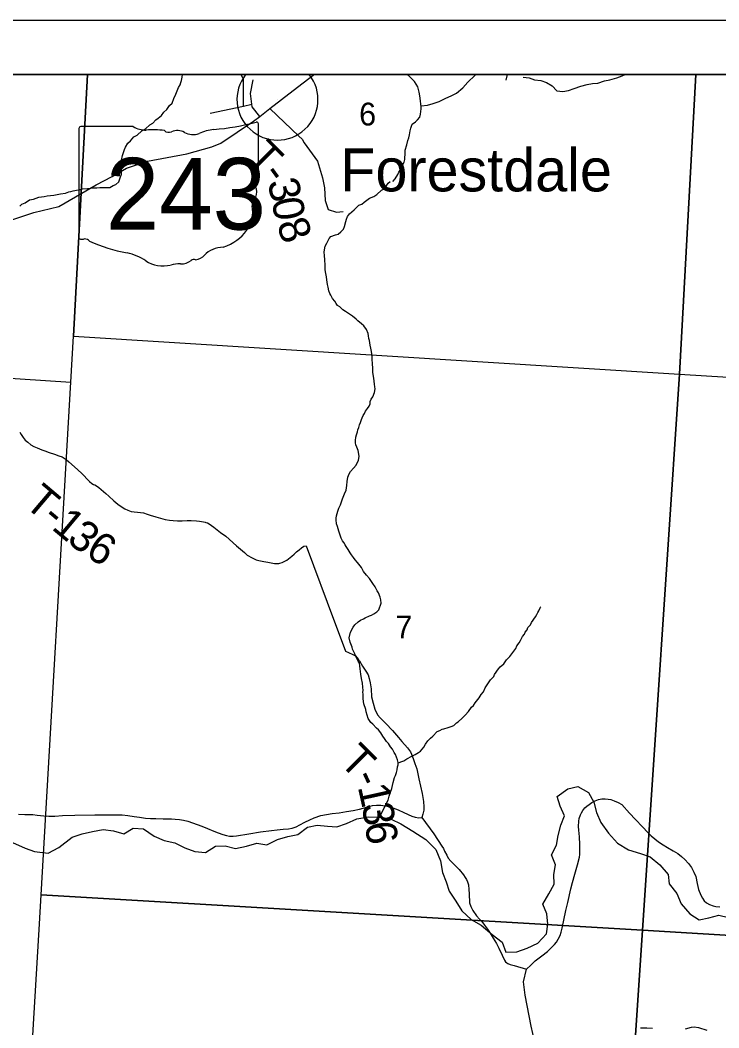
# Model space of a CAD drawing. Extents: x 0 to 45.4, y -2.2 to 22.
# Drawn here: x 2.846 to 4.13, y 19.147 to 21 of the extents above; entities that cross this region are included whole.
import ezdxf

# ---------------------------------------------------------------- set-up
doc = ezdxf.new("R2010")
doc.units = 0
for name, color, linetype in [('GM_X_Corporation', 7, 'Continuous'), ('GM_X_County_Road', 7, 'Continuous'), ('GM_X_Minor_River', 7, 'Continuous'), ('GM_X_Section_Text', 7, 'Continuous'), ('GM_X_State_Location', 7, 'Continuous'), ('GM_X_State_Route', 7, 'Continuous'), ('GM_X_State_Shield', 7, 'Continuous'), ('GM_X_Township_Road', 7, 'Continuous'), ('GM_X_Township_Road_Text', 7, 'Continuous'), ('GM_X_Unincorporated_Location', 7, 'Continuous'), ('GM_X_Unincorporated_Text', 7, 'Continuous'), ('GM_X_US_Shield', 7, 'Continuous'), ('SH_Data', 7, 'Continuous')]:
    doc.layers.add(name, color=color, linetype=linetype)

msp = doc.modelspace()

# ---------------------------------------------------------------- linework, layer by layer
at = {"layer": 'GM_X_Corporation'}
for points in [[(8.9, 20.9), (2.1, 20.9), (2.1, 19.3454), (2.1562, 19.32), (2.2951, 19.2289), (2.4503, 19.1527), (2.5862, 19.0536)], [(6.2942, 20.9), (2.1, 20.9), (2.1, 19.3454), (2.1562, 19.32), (2.2951, 19.2289), (2.4503, 19.1527), (2.5862, 19.0536)], [(2.8526, 18.8566), (2.8813, 19.3385), (2.8847, 19.3915), (3.9891, 19.3268), (3.9206, 18.2985)]]:
    msp.add_lwpolyline(points, dxfattribs=at)
for points in [[(2.9697, 20.9), (2.1, 20.9), (2.1, 20.3896), (2.9392, 20.3345), (2.9438, 20.419)], [(4.0874, 20.9), (2.9697, 20.9), (2.9438, 20.419), (4.0572, 20.3489)], [(5.1793, 20.9), (4.0874, 20.9), (4.0572, 20.3489), (5.1309, 20.2827)], [(2.9438, 20.419), (4.0572, 20.3489), (3.9891, 19.3268), (2.8847, 19.3915), (2.9392, 20.3345)], [(4.0572, 20.3489), (5.1309, 20.2827), (5.073, 19.2613), (3.9891, 19.3268)], [(5.073, 19.2613), (5.0121, 18.2353), (3.9206, 18.2985), (3.9891, 19.3268)]]:
    msp.add_lwpolyline(points, close=True, dxfattribs=at)
at = {"layer": 'GM_X_County_Road'}
msp.add_lwpolyline([(3.7907, 19.1234), (3.7847, 19.1505), (3.774, 19.2071), (3.7709, 19.2319), (3.7761, 19.2553), (3.784, 19.2626), (3.7924, 19.2704), (3.8044, 19.2797), (3.8148, 19.2874), (3.8227, 19.2954), (3.8279, 19.3004), (3.8314, 19.3046), (3.8344, 19.31), (3.8378, 19.3172), (3.8398, 19.3232), (3.8419, 19.3304), (3.8486, 19.3631), (3.852, 19.3775), (3.8578, 19.4026), (3.8607, 19.4146), (3.8651, 19.43), (3.8701, 19.4468), (3.8734, 19.4612), (3.8741, 19.4658), (3.874, 19.4842), (3.8736, 19.4985), (3.8726, 19.5108), (3.8719, 19.5175), (3.8721, 19.5274), (3.8731, 19.532), (3.8756, 19.539), (3.8772, 19.5426), (3.8799, 19.547), (3.8835, 19.5516), (3.8871, 19.555), (3.8912, 19.5579), (3.8965, 19.5616), (3.9026, 19.5648), (3.9083, 19.5669), (3.9149, 19.568), (3.9208, 19.5683), (3.926, 19.5677), (3.9314, 19.567), (3.9375, 19.5647), (3.9445, 19.5618), (3.9512, 19.5576), (3.9657, 19.5422), (3.9764, 19.5301), (3.9895, 19.5165), (3.9991, 19.5061), (4.0053, 19.5003), (4.0122, 19.4949), (4.0189, 19.4891), (4.0272, 19.4839), (4.0352, 19.4785), (4.0459, 19.4729), (4.054, 19.4676), (4.0608, 19.4624), (4.067, 19.4568), (4.0737, 19.4495), (4.0792, 19.4418), (4.0838, 19.4335), (4.0871, 19.4253), (4.0899, 19.4128), (4.0924, 19.4014), (4.0963, 19.3914), (4.0995, 19.3856), (4.1029, 19.3809), (4.1072, 19.3771), (4.1125, 19.374), (4.1189, 19.3715), (4.1243, 19.3705), (4.1315, 19.3699)], dxfattribs=at)
at = {"layer": 'GM_X_Minor_River'}
for points in [[(3.0338, 20.7514), (3.0377, 20.7624), (3.0393, 20.7665), (3.044, 20.7736), (3.0486, 20.7781), (3.0552, 20.7852), (3.0613, 20.7885), (3.0698, 20.7964), (3.0763, 20.8), (3.084, 20.8075), (3.0897, 20.8104), (3.0955, 20.8168), (3.0997, 20.8198), (3.1055, 20.8246), (3.1098, 20.831), (3.1155, 20.8355), (3.1206, 20.8433), (3.1256, 20.8471), (3.1284, 20.8561), (3.1319, 20.864), (3.1343, 20.8701), (3.1371, 20.8761), (3.1402, 20.881), (3.141, 20.8851), (3.1426, 20.8893), (3.1439, 20.895), (3.1444, 20.9)], [(3.531, 20.7031), (3.5352, 20.7083), (3.5399, 20.7162), (3.5419, 20.7204), (3.547, 20.7283), (3.5493, 20.7347), (3.5513, 20.7388), (3.5525, 20.7437), (3.5531, 20.7566), (3.5532, 20.7612), (3.5564, 20.771), (3.5584, 20.7786), (3.5601, 20.7838), (3.5613, 20.7891), (3.5625, 20.7963), (3.5638, 20.8016), (3.5662, 20.8088), (3.5723, 20.8129), (3.5762, 20.817), (3.58, 20.8219), (3.5816, 20.8271), (3.5826, 20.837), (3.583, 20.8412), (3.5824, 20.8457), (3.5817, 20.8514), (3.58, 20.8606), (3.579, 20.8678), (3.5769, 20.8773), (3.5706, 20.8873), (3.5654, 20.892), (3.5598, 20.8974), (3.5563, 20.9)], [(3.5829, 20.8423), (3.5943, 20.8435), (3.6049, 20.8466), (3.6158, 20.8507), (3.628, 20.8568), (3.6378, 20.8606), (3.6476, 20.8655), (3.659, 20.8757), (3.6685, 20.8859), (3.6813, 20.8984), (3.683, 20.9)], [(3.7699, 20.8951), (3.7809, 20.8939), (3.7911, 20.8901), (3.8028, 20.889), (3.8127, 20.8855), (3.8232, 20.8795), (3.8319, 20.87), (3.8429, 20.8689), (3.8535, 20.8708), (3.8641, 20.8742), (3.8759, 20.8787), (3.8876, 20.8814), (3.8974, 20.8833), (3.9073, 20.884), (3.9194, 20.8882), (3.9292, 20.8905), (3.9421, 20.8942), (3.9519, 20.8976), (3.9578, 20.9)], [(2.8454, 20.6578), (2.8492, 20.6619), (2.8553, 20.6641), (2.863, 20.6696), (2.8706, 20.671), (2.8801, 20.6747), (2.89, 20.676), (2.8957, 20.6771), (2.9078, 20.678), (2.9204, 20.6808), (2.9291, 20.6818), (2.9352, 20.6844), (2.9394, 20.6847), (2.9436, 20.6861), (2.9497, 20.6871), (2.9539, 20.6882), (2.9603, 20.6896), (2.9698, 20.6906), (2.9751, 20.6909), (2.9804, 20.6916), (2.9869, 20.6918), (2.9926, 20.6921), (2.9979, 20.6924), (3.0062, 20.6923), (3.0108, 20.6926), (3.0172, 20.6959), (3.0218, 20.6977), (3.0272, 20.7029), (3.03, 20.7101), (3.032, 20.7169), (3.0325, 20.7218), (3.033, 20.7298), (3.0323, 20.7347), (3.0321, 20.7427), (3.0338, 20.7514)], [(3.4738, 20.6619), (3.478, 20.6652), (3.4876, 20.6727), (3.496, 20.676), (3.5014, 20.6793), (3.5099, 20.6871), (3.5148, 20.6901), (3.5183, 20.6946), (3.5222, 20.7002), (3.5261, 20.7035)], [(3.4421, 20.1293), (3.4449, 20.1357), (3.4453, 20.1403), (3.4461, 20.1441), (3.447, 20.1517), (3.4483, 20.16), (3.4507, 20.166), (3.4527, 20.1702), (3.4584, 20.1761), (3.4631, 20.1818), (3.4674, 20.1908), (3.469, 20.1976), (3.4684, 20.2022), (3.4673, 20.2086), (3.4648, 20.2148), (3.4626, 20.2194), (3.4623, 20.2228), (3.4624, 20.227), (3.4629, 20.233), (3.4637, 20.2376), (3.4657, 20.2428), (3.4665, 20.247), (3.4681, 20.2512), (3.4697, 20.2561), (3.4713, 20.2602), (3.4729, 20.2655), (3.4741, 20.2689), (3.4761, 20.273), (3.4788, 20.2768), (3.4807, 20.2813), (3.4839, 20.2862), (3.487, 20.2903), (3.4889, 20.2945), (3.489, 20.299), (3.491, 20.3032), (3.4937, 20.3073), (3.4973, 20.3152), (3.4981, 20.322), (3.4978, 20.3258), (3.4971, 20.3308), (3.4958, 20.3418), (3.4948, 20.3483), (3.4941, 20.3525), (3.4942, 20.3563), (3.4939, 20.3608), (3.4936, 20.3677), (3.493, 20.3772), (3.4928, 20.3821), (3.4914, 20.3909), (3.49, 20.3966), (3.4889, 20.4023), (3.488, 20.4107), (3.4869, 20.4149), (3.4858, 20.4194), (3.4852, 20.424), (3.4823, 20.4313), (3.4774, 20.4378), (3.4733, 20.4417), (3.4666, 20.4471), (3.4633, 20.4502), (3.4565, 20.4556), (3.4528, 20.4584), (3.4438, 20.4642), (3.439, 20.4673), (3.4334, 20.4731), (3.4292, 20.4755), (3.4267, 20.4793), (3.4241, 20.4835), (3.42, 20.4882), (3.4171, 20.4943), (3.4149, 20.4977), (3.4134, 20.5023), (3.4117, 20.5088), (3.4106, 20.5141), (3.4096, 20.5225), (3.4086, 20.5282), (3.4076, 20.5343), (3.4065, 20.5412), (3.4063, 20.5495), (3.4057, 20.5594), (3.4051, 20.5674), (3.4048, 20.5731), (3.4049, 20.5776), (3.4062, 20.5845), (3.4093, 20.5901), (3.412, 20.595), (3.414, 20.5988), (3.4171, 20.6021), (3.4255, 20.605), (3.4304, 20.6068), (3.4354, 20.6105), (3.44, 20.6154), (3.442, 20.6207), (3.4441, 20.6298), (3.4453, 20.6339), (3.4477, 20.6392), (3.4512, 20.6437), (3.4554, 20.6478), (3.4596, 20.6511), (3.4685, 20.6597), (3.4738, 20.6619)], [(3.506, 19.5345), (3.5219, 19.5656), (3.5239, 19.5732), (3.5267, 19.5804), (3.5287, 19.5875), (3.53, 19.5928), (3.5316, 19.5981), (3.5336, 19.6072), (3.5356, 19.611), (3.5372, 19.6166), (3.5384, 19.6216), (3.5393, 19.6272), (3.5405, 19.631), (3.5402, 19.6352), (3.5395, 19.6398), (3.5373, 19.6447), (3.5355, 19.6497), (3.5333, 19.6532), (3.53, 19.6597), (3.5267, 19.6639), (3.523, 19.6697), (3.5189, 19.6739), (3.5152, 19.6793), (3.5126, 19.6835), (3.5089, 19.6893), (3.5041, 19.695), (3.5004, 19.6981), (3.4937, 19.7055), (3.49, 19.7086), (3.4878, 19.7124), (3.4856, 19.7162), (3.4816, 19.7285), (3.4809, 19.7323), (3.4773, 19.743), (3.476, 19.7521), (3.4761, 19.7604), (3.4758, 19.7642), (3.4759, 19.7677), (3.4756, 19.7737), (3.475, 19.781), (3.4732, 19.7894), (3.4722, 19.7977), (3.4709, 19.8072), (3.4698, 19.813), (3.4692, 19.8175), (3.4673, 19.8213), (3.4648, 19.8271), (3.4622, 19.8309), (3.4608, 19.8351), (3.4567, 19.8435), (3.4557, 19.847), (3.4521, 19.8565), (3.4507, 19.8645), (3.4531, 19.8747), (3.4578, 19.8838), (3.4609, 19.8879), (3.4671, 19.8935), (3.4713, 19.8965), (3.4767, 19.8994), (3.4801, 19.9009), (3.4881, 19.9049), (3.4916, 19.906), (3.4958, 19.9086), (3.5011, 19.9119), (3.505, 19.9156), (3.5094, 19.9281), (3.5087, 19.9342), (3.5073, 19.9391), (3.5044, 19.9472), (3.5018, 19.951), (3.5, 19.9544), (3.4982, 19.9583), (3.4937, 19.964), (3.4878, 19.9733), (3.4822, 19.9794), (3.4771, 19.9864), (3.4749, 19.9902), (3.4734, 19.9936), (3.4656, 20.0029), (3.4615, 20.0075), (3.4586, 20.0121), (3.4549, 20.0171), (3.4523, 20.0206), (3.4486, 20.0267), (3.4449, 20.0321), (3.4431, 20.0355), (3.4409, 20.0394), (3.4383, 20.0428), (3.4357, 20.0478), (3.4336, 20.0551), (3.4314, 20.0604), (3.4293, 20.0692), (3.4271, 20.0738), (3.4265, 20.081), (3.4265, 20.0844), (3.4274, 20.0886), (3.4298, 20.0973), (3.4318, 20.1029), (3.4345, 20.109), (3.4385, 20.1199), (3.4421, 20.1293)], [(3.5398, 19.6337), (3.5455, 19.6362), (3.5508, 19.6381), (3.5566, 19.6421), (3.5658, 19.6465), (3.5715, 19.6498), (3.578, 19.6535), (3.5818, 19.6561), (3.5876, 19.6632), (3.5908, 19.6689), (3.5951, 19.6749), (3.5997, 19.6801), (3.6039, 19.6835), (3.6124, 19.6921), (3.617, 19.6939), (3.6212, 19.6961), (3.6246, 19.6972), (3.6322, 19.6993), (3.6379, 19.7011), (3.6429, 19.7033), (3.6475, 19.7078), (3.651, 19.71), (3.6583, 19.7167), (3.6637, 19.7223), (3.6695, 19.7287), (3.6753, 19.7369), (3.6791, 19.7399), (3.6819, 19.7448), (3.6892, 19.7542), (3.6928, 19.7602), (3.6974, 19.765), (3.7005, 19.7722), (3.7103, 19.7868), (3.7164, 19.7932), (3.7177, 19.797), (3.725, 19.8071), (3.7277, 19.8108), (3.7347, 19.8164), (3.7393, 19.8236), (3.7459, 19.8299), (3.7513, 19.8374), (3.7564, 19.8445), (3.7587, 19.8494), (3.7626, 19.8551), (3.765, 19.8596), (3.7689, 19.8667), (3.7724, 19.8712), (3.7739, 19.875), (3.7774, 19.8791), (3.779, 19.8833), (3.7833, 19.8881), (3.7856, 19.8926), (3.7926, 19.9028), (3.7953, 19.9069), (3.7969, 19.9107), (3.7989, 19.9141), (3.802, 19.9205), (3.8025, 19.9211)], [(3.1301, 19.4873), (3.1483, 19.4781), (3.1672, 19.4712), (3.1868, 19.4697), (3.2051, 19.481), (3.2225, 19.4817), (3.2414, 19.477), (3.2619, 19.4815), (3.2808, 19.4868), (3.299, 19.4837), (3.3187, 19.4935), (3.3377, 19.4987), (3.3559, 19.5024), (3.3741, 19.516), (3.3915, 19.5198), (3.4105, 19.5182), (3.4279, 19.5166), (3.4453, 19.5226), (3.4643, 19.5316), (3.4863, 19.5354), (3.506, 19.5345), (3.5279, 19.5306), (3.5453, 19.5222), (3.5672, 19.5085), (3.5914, 19.4932), (3.6095, 19.4749), (3.6185, 19.4544), (3.6222, 19.4331), (3.6289, 19.4156), (3.6341, 19.3982), (3.6462, 19.3799), (3.6575, 19.3624), (3.6748, 19.3464), (3.693, 19.3357), (3.7133, 19.3189), (3.7314, 19.3044), (3.7382, 19.2862), (3.7586, 19.2869), (3.7776, 19.2936), (3.7973, 19.3027), (3.8133, 19.3201), (3.8156, 19.3375), (3.8135, 19.3565), (3.806, 19.3748), (3.8174, 19.3937), (3.8273, 19.4111), (3.8266, 19.4293), (3.8297, 19.4468), (3.8222, 19.465), (3.8314, 19.4832), (3.8345, 19.5007), (3.8391, 19.5196), (3.846, 19.5371), (3.8378, 19.5546), (3.8325, 19.5728), (3.8523, 19.5864), (3.8705, 19.5909), (3.8901, 19.5802), (3.8999, 19.5619), (3.9051, 19.5429), (3.9126, 19.5247), (3.9269, 19.5049), (3.9435, 19.4866), (3.9639, 19.4744), (3.9858, 19.4675), (4.0032, 19.4613), (4.0214, 19.4468), (4.0364, 19.4293), (4.0386, 19.4119), (4.0522, 19.3944), (4.0604, 19.3753), (4.0763, 19.3571), (4.0936, 19.3456), (4.1111, 19.3494), (4.1293, 19.3546), (4.1474, 19.35)], [(2.8317, 19.4877), (2.8552, 19.4777), (2.8726, 19.4716), (2.8975, 19.4684), (2.9173, 19.479), (2.9416, 19.4979), (2.9598, 19.5039), (2.9787, 19.5084), (2.9984, 19.5121), (3.0174, 19.5097), (3.0363, 19.5036), (3.0537, 19.5142), (3.0727, 19.5133), (3.0923, 19.4996), (3.1104, 19.4919), (3.1301, 19.4873)]]:
    msp.add_lwpolyline(points, dxfattribs=at)
at = {"layer": 'GM_X_State_Route'}
msp.add_lwpolyline([(2.7682, 20.604), (2.799, 20.6223), (2.8714, 20.6464), (2.9172, 20.6576), (2.9859, 20.6973), (3.015, 20.7125), (3.0417, 20.7277), (3.0797, 20.7405), (3.1523, 20.7541), (3.1983, 20.7669), (3.215, 20.7739), (3.2746, 20.8141), (3.2862, 20.8231), (3.3045, 20.8374), (3.3476, 20.8709), (3.3845, 20.8987), (3.387, 20.9)], dxfattribs=at)
at = {"layer": 'GM_X_State_Shield'}
for p, q in [((3.2837, 20.7046), (3.2837, 20.8093)), ((2.9541, 20.8009), (2.9541, 20.6007)), ((3.0539, 20.8043), (2.9574, 20.8043)), ((3.2837, 20.7046), (3.2837, 20.7046))]:
    msp.add_line(p, q, dxfattribs=at)
for centre, major_axis, start_param, end_param in [((3.1663, 21.0771), (0.3495, 0), 4.814394, 5.042369), ((3.28, 20.8097), (0.00367, 0), 6.141152, 7.989035), ((2.9579, 20.8013), (0.00382, 0), 1.712693, 3.28349), ((3.0769, 20.8275), (0.037, 0), 4.042523, 4.731795), ((3.0891, 20.692), (0.133, 0), 1.404758, 1.657858), ((3.1193, 20.8023), (0.0107, 0), 3.836095, 5.185415), ((3.135, 20.7792), (0.0222, 0), 0.950623, 2.079405), ((3.1637, 20.8109), (0.0267, 0), 4.081561, 5.145723), ((3.2109, 20.7432), (0.0703, 0), 1.699011, 2.107814), ((3.2829, 20.6969), (0.00568, 0), 1.883978, 3.671073), ((3.2798, 20.7042), (0.00393, 0), 5.05454, 6.418171), ((3.2467, 20.6837), (0.0341, 0), 5.934695, 6.695948), ((3.2968, 20.6608), (0.0248, 0), 2.387724, 3.262537), ((3.1859, 20.6475), (0.0874, 0), 5.101752, 6.440018), ((2.9579, 20.6003), (0.00385, 0), 3.00124, 4.508301), ((2.9585, 20.6208), (0.0294, 0), 4.665946, 4.897461), ((2.9645, 20.5892), (0.0106, 0), 0.519207, 1.627899), ((3.0983, 20.769), (0.2524, 0), 4.195997, 4.488961), ((3.0231, 20.5108), (0.079, 0), 0.823519, 1.323587), ((3.1621, 20.5814), (0.0282, 0), 4.937069, 5.64225), ((3.2227, 20.5446), (0.0479, 0), 1.647645, 2.488434), ((3.1085, 20.5882), (0.0501, 0), 4.026481, 4.996735), ((3.1375, 20.519), (0.0412, 0), 1.495662, 1.94098), ((3.1411, 20.5732), (0.0267, 0), 4.691044, 5.507374), ((3.1653, 20.5538), (0.00752, 0), 1.147584, 2.315152)]:
    msp.add_ellipse(centre, major_axis=major_axis, ratio=0.8, start_param=start_param, end_param=end_param, dxfattribs=at)
at = {"layer": 'GM_X_Township_Road'}
msp.add_line((3.7388, 20.8896), (3.7415, 20.9), dxfattribs=at)
for points in [[(3.2566, 20.8421), (3.2564, 20.8908), (3.2523, 20.9)], [(3.2862, 20.8231), (3.2724, 20.8404), (3.2718, 20.8454), (3.2694, 20.8651), (3.274, 20.8902)], [(3.1949, 20.8287), (3.2566, 20.8421), (3.2718, 20.8454)], [(3.3045, 20.8374), (3.3578, 20.7869), (3.3643, 20.7812), (3.3677, 20.7747), (3.3923, 20.7407), (3.4014, 20.7103), (3.4052, 20.6917), (3.4063, 20.6682), (3.412, 20.6518), (3.4272, 20.6469), (3.4397, 20.6484)], [(2.8452, 20.2423), (2.848, 20.238), (2.8514, 20.2327), (2.8555, 20.2279), (2.8599, 20.2238), (2.8654, 20.2191), (2.8712, 20.216), (2.8774, 20.2135), (2.886, 20.2102), (2.8913, 20.2084), (2.8992, 20.2053), (2.909, 20.202), (2.9172, 20.1992), (2.9231, 20.1969), (2.9306, 20.1919), (2.9356, 20.1877), (2.9459, 20.1784), (2.9586, 20.167), (2.9735, 20.1519), (2.9779, 20.1478), (2.9809, 20.1462), (2.9833, 20.1454), (2.9862, 20.1438), (2.9903, 20.1407), (3.0034, 20.1298), (3.0091, 20.1247), (3.0184, 20.1162), (3.0252, 20.1103), (3.0336, 20.1046), (3.0381, 20.1016), (3.044, 20.0988), (3.0499, 20.0964), (3.0553, 20.0957), (3.0615, 20.0953), (3.0671, 20.0949), (3.0729, 20.0939), (3.0792, 20.0919), (3.0846, 20.0896), (3.0956, 20.0866), (3.1039, 20.0843), (3.1125, 20.082), (3.1203, 20.0806), (3.1274, 20.0798), (3.1349, 20.0797), (3.1437, 20.0796), (3.1526, 20.08), (3.1604, 20.0802), (3.1702, 20.0796), (3.1755, 20.079), (3.1793, 20.0784), (3.1831, 20.0778), (3.1858, 20.077), (3.1874, 20.0763), (3.1905, 20.0757), (3.1934, 20.0736), (3.2019, 20.0678), (3.2144, 20.0582), (3.2238, 20.0511), (3.2438, 20.0332), (3.258, 20.0209), (3.2634, 20.016), (3.2722, 20.0111), (3.2795, 20.008), (3.2847, 20.0066), (3.2936, 20.0045), (3.3013, 20.0035), (3.3131, 20.0012), (3.3178, 20.0007), (3.321, 20.0009), (3.3234, 20.0016), (3.3277, 20.0029), (3.3358, 20.0072), (3.3453, 20.0144), (3.3495, 20.0183), (3.3539, 20.0222), (3.3584, 20.0261), (3.3632, 20.0298), (3.3673, 20.0326), (3.3717, 20.0332), (3.4234, 19.894), (3.4248, 19.8905)], [(3.4248, 19.8905), (3.4436, 19.8397), (3.4491, 19.8376), (3.4572, 19.8339), (3.4621, 19.8313), (3.4652, 19.8277), (3.4679, 19.824), (3.4692, 19.8218), (3.475, 19.8119), (3.4811, 19.8028), (3.4854, 19.7961), (3.4875, 19.7898), (3.489, 19.7815), (3.4908, 19.7702), (3.4918, 19.7558), (3.4946, 19.744), (3.4978, 19.7329), (3.5025, 19.7226), (3.5072, 19.7172)], [(3.5072, 19.7172), (3.5086, 19.7157), (3.5176, 19.7069), (3.5303, 19.6936), (3.5412, 19.6813), (3.5472, 19.6737), (3.5575, 19.6619), (3.5629, 19.6549), (3.5651, 19.6503), (3.5683, 19.6425), (3.5714, 19.6333), (3.5746, 19.6237), (3.5784, 19.6053), (3.5846, 19.5781), (3.5871, 19.5634), (3.5875, 19.5534), (3.5875, 19.5475), (3.586, 19.5402), (3.5841, 19.5341)], [(2.8433, 19.54), (2.8545, 19.5397), (2.8696, 19.5395), (2.8776, 19.5385), (2.8898, 19.5371), (2.8986, 19.5366), (2.9096, 19.5365), (2.9241, 19.5375), (2.9463, 19.5382), (2.9832, 19.5386), (3.0239, 19.5389), (3.0332, 19.5386), (3.0438, 19.5375), (3.0553, 19.5359), (3.0652, 19.5344), (3.0762, 19.5328), (3.0855, 19.5321), (3.0956, 19.5318), (3.1086, 19.5316), (3.1243, 19.5314), (3.1311, 19.5311), (3.1388, 19.5303), (3.1459, 19.5293), (3.154, 19.5273), (3.1624, 19.5244), (3.1797, 19.518), (3.1902, 19.5137), (3.2016, 19.5089), (3.21, 19.5056), (3.2186, 19.5026), (3.2251, 19.5006), (3.2309, 19.4999), (3.2372, 19.4996), (3.2437, 19.5001), (3.266, 19.5036), (3.2878, 19.5077), (3.3078, 19.5102), (3.3182, 19.5115), (3.3292, 19.5123), (3.3389, 19.5132), (3.3455, 19.5144), (3.3533, 19.5167), (3.3601, 19.5203), (3.3688, 19.5252), (3.378, 19.5299), (3.3864, 19.5334), (3.3987, 19.5376), (3.4086, 19.5396), (3.4191, 19.5411), (3.4324, 19.5428), (3.4458, 19.5447), (3.4579, 19.5467), (3.4692, 19.5492), (3.485, 19.5535), (3.4933, 19.5557), (3.5004, 19.5568), (3.5084, 19.5567), (3.5204, 19.5545), (3.5307, 19.5515), (3.5403, 19.5478), (3.5508, 19.5429), (3.5653, 19.5363), (3.5716, 19.5343), (3.5786, 19.5334), (3.5841, 19.5341), (3.6059, 19.5038), (3.6206, 19.4815), (3.6236, 19.4768), (3.6259, 19.4718), (3.6299, 19.4648), (3.6323, 19.4589), (3.6372, 19.4537), (3.6526, 19.4385), (3.6603, 19.4288), (3.6636, 19.4239), (3.6663, 19.4199), (3.668, 19.4158), (3.6695, 19.4099), (3.6706, 19.4016), (3.6707, 19.3936), (3.6718, 19.3769), (3.6739, 19.3703), (3.6778, 19.3631), (3.6841, 19.3532), (3.69, 19.3472), (3.6943, 19.3424), (3.6991, 19.336), (3.7049, 19.3285), (3.7097, 19.3211), (3.7151, 19.3123), (3.7212, 19.302), (3.7252, 19.2935), (3.7317, 19.2805), (3.7356, 19.2718), (3.7377, 19.2685), (3.7401, 19.2667), (3.742, 19.2656), (3.7465, 19.2637), (3.7534, 19.2616), (3.7761, 19.2553)], [(3.9856, 19.147), (3.9975, 19.1473), (4.0079, 19.1464)], [(4.0686, 19.1454), (4.0796, 19.1483), (4.084, 19.1489), (4.0925, 19.1477), (4.1076, 19.1429)]]:
    msp.add_lwpolyline(points, dxfattribs=at)
at = {"layer": 'GM_X_Unincorporated_Location'}
msp.add_line((3.3188, 20.854), (3.3188, 20.854), dxfattribs=at)
at = {"layer": 'GM_X_US_Shield'}
msp.add_line((3.3773, 20.9), (3.2603, 20.9), dxfattribs=at)
msp.add_arc((3.3188, 20.854), 0.0744, 141.8409, 38.1591, dxfattribs=at)
at = {"layer": 'SH_Data'}
for p, q in [((2, 21), (9, 21)), ((2.1, 20.9), (8.9, 20.9))]:
    msp.add_line(p, q, dxfattribs=at)

# ---------------------------------------------------------------- texts
at = {"layer": 'GM_X_Section_Text'}
for s, p in [('6', (3.4688, 20.8064)), ('7', (3.5354, 19.8632))]:
    msp.add_text(s, height=0.0419, rotation=0, dxfattribs=at).set_placement(p)
at = {"layer": 'GM_X_State_Location'}
for s in ['s', 'r']:
    msp.add_text(s, height=0.000189, dxfattribs=at).set_placement((3.1152, 20.6875))
msp.add_text('243', height=0.000189, rotation=0, dxfattribs=at).set_placement((3.0483, 20.6737))
at = {"layer": 'GM_X_State_Shield'}
msp.add_text('243', height=0.13184, dxfattribs=at).set_placement((3.0036, 20.6149))
at = {"layer": 'GM_X_Township_Road_Text'}
for s, rotation, p in [('T', 314.7174, (3.2601, 20.7447)), ('-', 305.9476, (3.2885, 20.7163)), ('3', 283.5683, (3.2998, 20.7027)), ('0', 280.0323, (3.3078, 20.6696)), ('8', 289.4798, (3.3165, 20.6252)), ('T', 319.7289, (2.8513, 20.1082)), ('-', 319.8049, (2.8837, 20.0807)), ('1', 320.1435, (2.9019, 20.0654)), ('3', 321.2677, (2.9297, 20.0422)), ('6', 328.8432, (2.9637, 20.0156)), ('T', 315.014, (3.4303, 19.6345)), ('-', 294.8708, (3.4573, 19.6088)), ('1', 282.4413, (3.4661, 19.5907)), ('3', 279.1194, (3.4735, 19.5574)), ('6', 278.5768, (3.479, 19.523))]:
    msp.add_text(s, height=0.0568, rotation=rotation, dxfattribs=at).set_placement(p)
at = {"layer": 'GM_X_Unincorporated_Text'}
msp.add_text('Forestdale', height=0.07898, rotation=0, dxfattribs=at).set_placement((3.4342, 20.6851))

doc.saveas('drawing.dxf')
